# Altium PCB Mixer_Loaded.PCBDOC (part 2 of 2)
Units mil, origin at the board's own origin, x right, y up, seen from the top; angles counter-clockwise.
Board outline 16350 x 11350 mil, 2 copper layers (Top Layer, Bottom Layer); 554 components, 386 nets, 1551 pads, 0 vias.
Unrouted connection lines stored in the file: 1047.
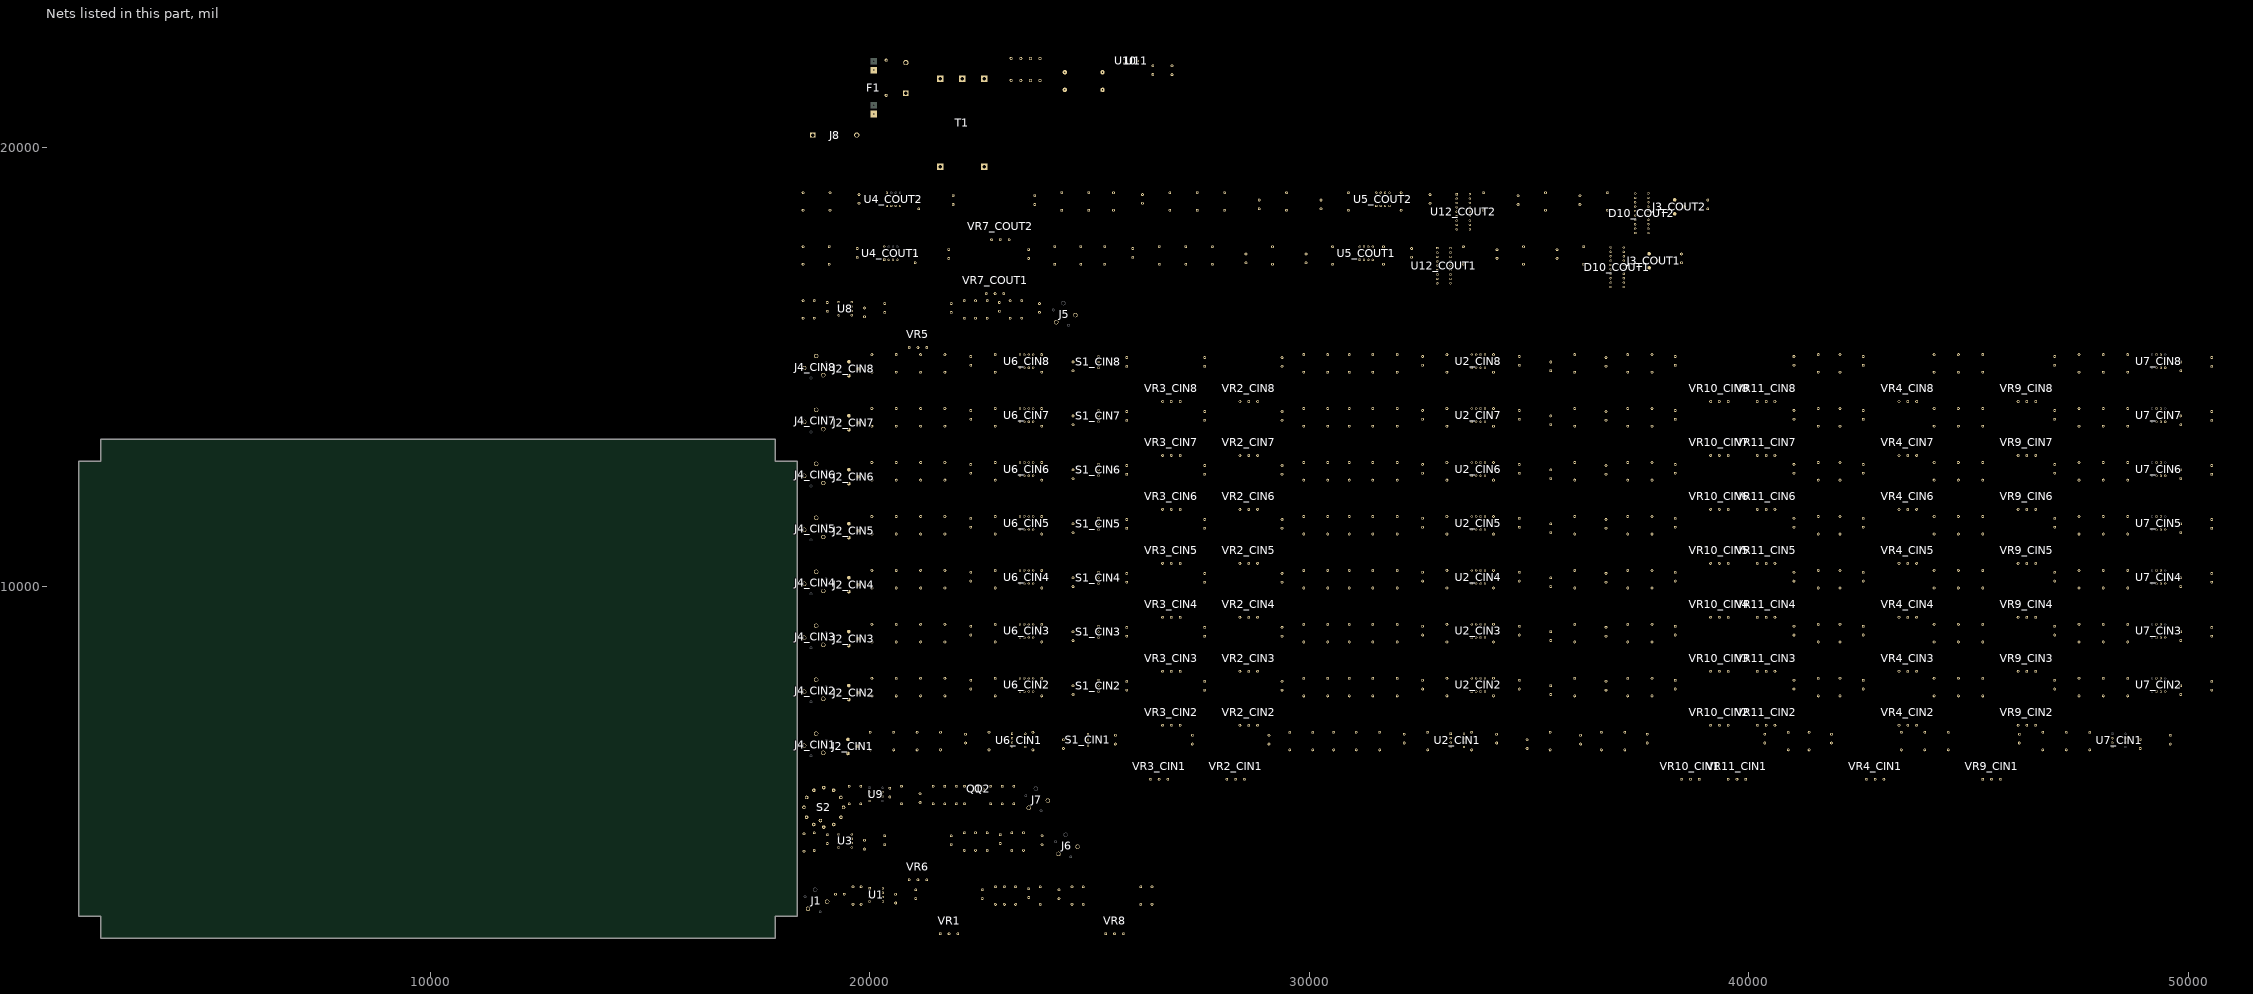
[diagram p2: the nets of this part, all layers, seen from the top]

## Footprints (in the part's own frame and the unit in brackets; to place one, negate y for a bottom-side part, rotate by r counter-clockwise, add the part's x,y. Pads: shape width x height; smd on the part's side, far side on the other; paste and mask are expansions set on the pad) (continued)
FUSE [mil]
  rect 150x150 hole 30: 1(0,0) 1(200,0) 2(1000,0) 2(1200,0)
  Top Layer region: 150,75 50,75 50,-75 150,-75
  Top Layer region: 1150,75 1050,75 1050,-75 1150,-75
  Bottom Layer region: 150,75 50,75 50,-75 150,-75
  Bottom Layer region: 1150,75 1050,75 1050,-75 1150,-75
  silkscreen extent -100,-100 1300,100
IEC-MAINS [mil]
  rect 120x120 hole 80: 1(0,0)
  round 120 hole 80: 2(500,0) 3(1000,0)
  silkscreen extent -250,-250 1250,1750
JACK-6.25MM [mil]
  round 60 hole 39: 0(-251,94) 0(94,-251)
  round 100 hole 78: 1(251,-22) 2(-22,251) 3(-184,-184)
  silkscreen extent -315,-315 315,315
"LED - 10 BAR HORIZONTAL" [mil]
  rect 50x50 hole 32: 1(0,0)
  round 50 hole 32: 2(300,0) 3(0,100) 4(300,100) 5(0,200) 6(300,200) 7(0,300) 8(300,300) 9(0,400) 10(300,400) 11(0,500) 12(300,500) 13(0,600) 14(300,600) 15(0,700) 16(300,700) 17(0,800) 18(300,800) 19(0,900) 20(300,900)
  silkscreen extent -50,-50 350,950
"POT - 24MM" [mil]
  round 62 hole 35: 1(-200,-600) 2(0,-600) 3(200,-600)
  round 50 hole 236.22 unplated: MNT(0,0)
  Keep-Out Layer circle w10: c0,0 r210
  silkscreen extent -500,-670 500,500
RAD0.2 [mil]
  round 62 hole 28: 1(0,0) 2(200,0)
  silkscreen extent -75,-75 275,75
RAD0.8 [mil]
  round 70 hole 40: 1(0,0) 2(800,0)
  silkscreen extent -75,-125 875,125
RB.2/.4 [mil]
  round 62 hole 28: 1(0,0) 2(-200,0)
  silkscreen extent -300,-200 200,200
RB.2/.4-NP [mil]
  round 62 hole 28: 1(0,0) 2(-200,0)
  silkscreen extent -300,-200 100,200
RB.4/.8 [mil]
  round 100 hole 28: 1(0,0) 2(-400,0)
  silkscreen extent -600,-400 350,400
SW-12WAY [mil]
  round 80 hole 40: 1(225,389.71) 2(389.71,225) 3(450,0) 4(389.71,-225) 5(225,-389.71) 6(0,-450) 7(-225,-389.71) 8(-389.71,-225) 9(-450,0) 10(-389.71,225) 11(-225,389.71) 12(0,450) 13(-75,-300)
  silkscreen extent -500,-500 500,500
SW-MAINS [mil]
  rect 120x120 hole 80: 1(0,0)
  round 120 hole 80: 2(700,0)
  silkscreen extent -120,-225 830,225
SW-SPDT [mil]
  rect 50x50 hole 32: 1(0,0)
  round 50 hole 32: 2(130,0) 3(260,0)
  silkscreen extent -70,-75 330,75
TO-92A [mil]
  round 50 hole 30: 1(0,0) 2(50,-50) 3(100,0)
  silkscreen extent -40,-90 140,40
TRANSFORMER [mil]
  rect 150x150 hole 80: 1(0,0) 2(0,1000) 3(2000,1000) 4(2000,500) 5(2000,0)
  silkscreen extent -500,-500 2500,1500
XLR-FEMALE [mm]
  round 2.032 smd: 1(-4.05,0.8) 2(4.05,0.8) 3(0,-4.7)
  silkscreen extent -9,-9 9,9
XLR-MALE [mm]
  round 2.032 smd: 1(4.05,0.8) 2(-4.05,0.8) 3(0,-4.7)
  silkscreen extent -9,-9 9,9

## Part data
C1 C2 C3 C4 C5 C6 C7_CIN1 C7_CIN2 C7_CIN3 C7_CIN4 C7_CIN5 C7_CIN6 C7_CIN7 C7_CIN8 C8_CIN1 C8_CIN2 C8_CIN3 C8_CIN4 C8_CIN5 C8_CIN6 C8_CIN7 C8_CIN8 C9_CIN1 C9_CIN2 C9_CIN3 C9_CIN4 C9_CIN5 C9_CIN6 C9_CIN7 C9_CIN8 C10_CIN1 C10_CIN2 C10_CIN3 C10_CIN4 C10_CIN5 C10_CIN6 C10_CIN7 C10_CIN8 C11 C12 C13_COUT1 C13_COUT2 C14_COUT1 C14_COUT2 C24 C25_CIN1 C25_CIN2 C25_CIN3 C25_CIN4 C25_CIN5 C25_CIN6 C25_CIN7 C25_CIN8 C26_CIN1 C26_CIN2 C26_CIN3 C26_CIN4 C26_CIN5 C26_CIN6 C26_CIN7 C26_CIN8 C27_CIN1 C27_CIN2 C27_CIN3 C27_CIN4 C27_CIN5 C27_CIN6 C27_CIN7 C27_CIN8 C28_COUT1 C28_COUT2 C29_CIN1 C29_CIN2 C29_CIN3 C29_CIN4 C29_CIN5 C29_CIN6 C29_CIN7 C29_CIN8 C30_CIN1 C30_CIN2 C30_CIN3 C30_CIN4 C30_CIN5 C30_CIN6 C30_CIN7 C30_CIN8 C31_CIN1 C31_CIN2 C31_CIN3 C31_CIN4 C31_CIN5 C31_CIN6 C31_CIN7 C31_CIN8 C32_CIN1 C32_CIN2 C32_CIN3 C32_CIN4 C32_CIN5 C32_CIN6 C32_CIN7 C32_CIN8 C33_CIN1 C33_CIN2 C33_CIN3 C33_CIN4 C33_CIN5 C33_CIN6 C33_CIN7 C33_CIN8 C34 C35 C36_COUT1 C36_COUT2 C37 C38 C39_COUT1 C39_COUT2 C40_COUT1 C40_COUT2 C41 C42 C43 C44 C51_COUT1 C51_COUT2: "Capacitor"
C15 C16_CIN1 C16_CIN2 C16_CIN3 C16_CIN4 C16_CIN5 C16_CIN6 C16_CIN7 C16_CIN8 C17_CIN1 C17_CIN2 C17_CIN3 C17_CIN4 C17_CIN5 C17_CIN6 C17_CIN7 C17_CIN8 C18_CIN1 C18_CIN2 C18_CIN3 C18_CIN4 C18_CIN5 C18_CIN6 C18_CIN7 C18_CIN8 C19 C20 C21 C22_COUT1 C22_COUT2 C23_COUT1 C23_COUT2 C45 C46 C47 C48 C49_COUT1 C49_COUT2 C50_COUT1 C50_COUT2: "Bi-Polar Capacitor"
D1 D2 D3 D4 D5 D6: "Diode"
F1: "Fuse"
J2_CIN1 J2_CIN2 J2_CIN3 J2_CIN4 J2_CIN5 J2_CIN6 J2_CIN7 J2_CIN8 J3_COUT1 J3_COUT2: "XLR connector, PCB mounted"
J8: "Connector"
Q1: "NPN BJT"
Q2: "PNP BJT"
R1 R2 R3_CIN1 R3_CIN2 R3_CIN3 R3_CIN4 R3_CIN5 R3_CIN6 R3_CIN7 R3_CIN8 R4_CIN1 R4_CIN2 R4_CIN3 R4_CIN4 R4_CIN5 R4_CIN6 R4_CIN7 R4_CIN8 R5_CIN1 R5_CIN2 R5_CIN3 R5_CIN4 R5_CIN5 R5_CIN6 R5_CIN7 R5_CIN8 R6_CIN1 R6_CIN2 R6_CIN3 R6_CIN4 R6_CIN5 R6_CIN6 R6_CIN7 R6_CIN8 R7 R8_COUT1 R8_COUT2 R9 R10 R11_CIN1 R11_CIN2 R11_CIN3 R11_CIN4 R11_CIN5 R11_CIN6 R11_CIN7 R11_CIN8 R12_CIN1 R12_CIN2 R12_CIN3 R12_CIN4 R12_CIN5 R12_CIN6 R12_CIN7 R12_CIN8 R13 R14 R15_COUT1 R15_COUT2 R16 R17 R18 R19 R20_CIN1 R20_CIN2 R20_CIN3 R20_CIN4 R20_CIN5 R20_CIN6 R20_CIN7 R20_CIN8 R21_CIN1 R21_CIN2 R21_CIN3 R21_CIN4 R21_CIN5 R21_CIN6 R21_CIN7 R21_CIN8 R22_CIN1 R22_CIN2 R22_CIN3 R22_CIN4 R22_CIN5 R22_CIN6 R22_CIN7 R22_CIN8 R23_CIN1 R23_CIN2 R23_CIN3 R23_CIN4 R23_CIN5 R23_CIN6 R23_CIN7 R23_CIN8 R24 R25_CIN1 R25_CIN2 R25_CIN3 R25_CIN4 R25_CIN5 R25_CIN6 R25_CIN7 R25_CIN8 R26_CIN1 R26_CIN2 R26_CIN3 R26_CIN4 R26_CIN5 R26_CIN6 R26_CIN7 R26_CIN8 R27_CIN1 R27_CIN2 R27_CIN3 R27_CIN4 R27_CIN5 R27_CIN6 R27_CIN7 R27_CIN8 R28_CIN1 R28_CIN2 R28_CIN3 R28_CIN4 R28_CIN5 R28_CIN6 R28_CIN7 R28_CIN8 R29 R30 R31 R32 R33 R34 R35 R36 R37_COUT1 R37_COUT2 R38_COUT1 R38_COUT2 R39 R40_CIN1 R40_CIN2 R40_CIN3 R40_CIN4 R40_CIN5 R40_CIN6 R40_CIN7 R40_CIN8 R41_CIN1 R41_CIN2 R41_CIN3 R41_CIN4 R41_CIN5 R41_CIN6 R41_CIN7 R41_CIN8 R42_COUT1 R42_COUT2 R43_CIN1 R43_CIN2 R43_CIN3 R43_CIN4 R43_CIN5 R43_CIN6 R43_CIN7 R43_CIN8 R44_COUT1 R44_COUT2 R45_CIN1 R45_CIN2 R45_CIN3 R45_CIN4 R45_CIN5 R45_CIN6 R45_CIN7 R45_CIN8 R46_CIN1 R46_CIN2 R46_CIN3 R46_CIN4 R46_CIN5 R46_CIN6 R46_CIN7 R46_CIN8 R47_CIN1 R47_CIN2 R47_CIN3 R47_CIN4 R47_CIN5 R47_CIN6 R47_CIN7 R47_CIN8 R48_CIN1 R48_CIN2 R48_CIN3 R48_CIN4 R48_CIN5 R48_CIN6 R48_CIN7 R48_CIN8 R49_CIN1 R49_CIN2 R49_CIN3 R49_CIN4 R49_CIN5 R49_CIN6 R49_CIN7 R49_CIN8 R50_CIN1 R50_CIN2 R50_CIN3 R50_CIN4 R50_CIN5 R50_CIN6 R50_CIN7 R50_CIN8 R51_CIN1 R51_CIN2 R51_CIN3 R51_CIN4 R51_CIN5 R51_CIN6 R51_CIN7 R51_CIN8 R52 R53 R54 R55_COUT1 R55_COUT2 R56_COUT1 R56_COUT2 R57 R58 R59 R60_COUT1 R60_COUT2 R61 R62 R63_COUT1 R63_COUT2 R64_COUT1 R64_COUT2 R65_COUT1 R65_COUT2 R66 R67 R68 R69_COUT1 R69_COUT2 R70_COUT1 R70_COUT2: "Resistor"
T1: "Center-Tapped Transformer"
U1 U2_CIN1 U2_CIN2 U2_CIN3 U2_CIN4 U2_CIN5 U2_CIN6 U2_CIN7 U2_CIN8 U3 U4_COUT1 U4_COUT2 U5_COUT1 U5_COUT2 U8: "Fast Settling Dual Operational Amplifier"
U6_CIN1 U6_CIN2 U6_CIN3 U6_CIN4 U6_CIN5 U6_CIN6 U6_CIN7 U6_CIN8: "Self-Contained Audio Preamplifier"
U7_CIN1 U7_CIN2 U7_CIN3 U7_CIN4 U7_CIN5 U7_CIN6 U7_CIN7 U7_CIN8: "Low Noise, High Speed Precision Operational Amplifier"
U9: "Low-Noise  JFET-Input Operational Amplifiers"
U10 U11: "Very Low Drop Voltage Regulators With Inhibit"
U12_COUT1 U12_COUT2: "Dot/Bar Display Driver"
VR1 VR2_CIN1 VR2_CIN2 VR2_CIN3 VR2_CIN4 VR2_CIN5 VR2_CIN6 VR2_CIN7 VR2_CIN8 VR3_CIN1 VR3_CIN2 VR3_CIN3 VR3_CIN4 VR3_CIN5 VR3_CIN6 VR3_CIN7 VR3_CIN8 VR4_CIN1 VR4_CIN2 VR4_CIN3 VR4_CIN4 VR4_CIN5 VR4_CIN6 VR4_CIN7 VR4_CIN8 VR5 VR6 VR7_COUT1 VR7_COUT2 VR8 VR9_CIN1 VR9_CIN2 VR9_CIN3 VR9_CIN4 VR9_CIN5 VR9_CIN6 VR9_CIN7 VR9_CIN8 VR10_CIN1 VR10_CIN2 VR10_CIN3 VR10_CIN4 VR10_CIN5 VR10_CIN6 VR10_CIN7 VR10_CIN8 VR11_CIN1 VR11_CIN2 VR11_CIN3 VR11_CIN4 VR11_CIN5 VR11_CIN6 VR11_CIN7 VR11_CIN8: "Potentiometer"

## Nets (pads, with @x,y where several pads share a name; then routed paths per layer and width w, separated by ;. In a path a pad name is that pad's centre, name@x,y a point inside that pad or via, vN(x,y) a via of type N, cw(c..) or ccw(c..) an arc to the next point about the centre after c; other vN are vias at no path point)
+15V: C15.1 C16_CIN1.1 C16_CIN2.1 C16_CIN3.1 C16_CIN4.1 C16_CIN5.1 C16_CIN6.1 C16_CIN7.1 C16_CIN8.1 C17_CIN1.1 C17_CIN2.1 C17_CIN3.1 C17_CIN4.1 C17_CIN5.1 C17_CIN6.1 C17_CIN7.1 C17_CIN8.1 C18_CIN1.1 C18_CIN2.1 C18_CIN3.1 C18_CIN4.1 C18_CIN5.1 C18_CIN6.1 C18_CIN7.1 C18_CIN8.1 C19.1 C20.1 C21.1 C22_COUT1.1 C22_COUT2.1 C23_COUT1.1 C23_COUT2.1 C47.1 C49_COUT1.1 C49_COUT2.1 Q1.1 R53.2 R69_COUT1.1 R69_COUT2.1 U1.4 U2_CIN1.8 U2_CIN2.8 U2_CIN3.8 U2_CIN4.8 U2_CIN5.8 U2_CIN6.8 U2_CIN7.8 U2_CIN8.8 U3.8 U4_COUT1.8 U4_COUT2.8 U5_COUT1.8 U5_COUT2.8 U6_CIN1.7 U6_CIN2.7 U6_CIN3.7 U6_CIN4.7 U6_CIN5.7 U6_CIN6.7 U6_CIN7.7 U6_CIN8.7 U7_CIN1.7 U7_CIN2.7 U7_CIN3.7 U7_CIN4.7 U7_CIN5.7 U7_CIN6.7 U7_CIN7.7 U7_CIN8.7 U8.8 U9.7 U10.3 U12_COUT1.3 U12_COUT1.9 U12_COUT2.3 U12_COUT2.9
-15V: C15.2 C16_CIN1.2 C16_CIN2.2 C16_CIN3.2 C16_CIN4.2 C16_CIN5.2 C16_CIN6.2 C16_CIN7.2 C16_CIN8.2 C17_CIN1.2 C17_CIN2.2 C17_CIN3.2 C17_CIN4.2 C17_CIN5.2 C17_CIN6.2 C17_CIN7.2 C17_CIN8.2 C18_CIN1.2 C18_CIN2.2 C18_CIN3.2 C18_CIN4.2 C18_CIN5.2 C18_CIN6.2 C18_CIN7.2 C18_CIN8.2 C19.2 C20.2 C21.2 C22_COUT1.2 C22_COUT2.2 C23_COUT1.2 C23_COUT2.2 C48.2 Q2.1 R54.1 U1.8 U2_CIN1.4 U2_CIN2.4 U2_CIN3.4 U2_CIN4.4 U2_CIN5.4 U2_CIN6.4 U2_CIN7.4 U2_CIN8.4 U3.4 U4_COUT1.4 U4_COUT2.4 U5_COUT1.4 U5_COUT2.4 U6_CIN1.4 U6_CIN2.4 U6_CIN3.4 U6_CIN4.4 U6_CIN5.4 U6_CIN6.4 U6_CIN7.4 U6_CIN8.4 U7_CIN1.4 U7_CIN2.4 U7_CIN3.4 U7_CIN4.4 U7_CIN5.4 U7_CIN6.4 U7_CIN7.4 U7_CIN8.4 U8.4 U9.4 U11.1
A_FUSE: C44.2 F1.2@20087,21753 S3.2
A_IN: F1.1@20087,20753 J8.1
A_SWITCH: C44.1 S3.1 T1.1
GND: C45.2 C46.1 C47.2 C48.1 C49_COUT1.2 C49_COUT2.2 C50_COUT1.2 C50_COUT2.2 J1.3 J2_CIN1.1 J2_CIN2.1 J2_CIN3.1 J2_CIN4.1 J2_CIN5.1 J2_CIN6.1 J2_CIN7.1 J2_CIN8.1 J3_COUT1.1 J3_COUT2.1 J4_CIN1.3 J4_CIN2.3 J4_CIN3.3 J4_CIN4.3 J4_CIN5.3 J4_CIN6.3 J4_CIN7.3 J4_CIN8.3 J5.3 J6.3 J7.3 R1.1 R2.1 R3_CIN1.2 R3_CIN2.2 R3_CIN3.2 R3_CIN4.2 R3_CIN5.2 R3_CIN6.2 R3_CIN7.2 R3_CIN8.2 R7.1 R8_COUT1.1 R8_COUT2.1 R24.2 R27_CIN1.1 R27_CIN2.1 R27_CIN3.1 R27_CIN4.1 R27_CIN5.1 R27_CIN6.1 R27_CIN7.1 R27_CIN8.1 R28_CIN1.1 R28_CIN2.1 R28_CIN3.1 R28_CIN4.1 R28_CIN5.1 R28_CIN6.1 R28_CIN7.1 R28_CIN8.1 R30.1 R31.2 R34.1 R35.2 R38_COUT1.2 R38_COUT2.2 R48_CIN1.1 R48_CIN2.1 R48_CIN3.1 R48_CIN4.1 R48_CIN5.1 R48_CIN6.1 R48_CIN7.1 R48_CIN8.1 R49_CIN1.1 R49_CIN2.1 R49_CIN3.1 R49_CIN4.1 R49_CIN5.1 R49_CIN6.1 R49_CIN7.1 R49_CIN8.1 R70_COUT1.1 R70_COUT2.1 T1.4 U3.3 U4_COUT1.3 U4_COUT2.3 U5_COUT1.3 U5_COUT2.3 U6_CIN1.5 U6_CIN2.5 U6_CIN3.5 U6_CIN4.5 U6_CIN5.5 U6_CIN6.5 U6_CIN7.5 U6_CIN8.5 U7_CIN1.3 U7_CIN2.3 U7_CIN3.3 U7_CIN4.3 U7_CIN5.3 U7_CIN6.3 U7_CIN7.3 U7_CIN8.3 U8.3 U10.2 U11.3 U12_COUT1.2 U12_COUT1.4 U12_COUT2.2 U12_COUT2.4 VR1.3 VR2_CIN1.3 VR2_CIN2.3 VR2_CIN3.3 VR2_CIN4.3 VR2_CIN5.3 VR2_CIN6.3 VR2_CIN7.3 VR2_CIN8.3 VR3_CIN1.3 VR3_CIN2.3 VR3_CIN3.3 VR3_CIN4.3 VR3_CIN5.3 VR3_CIN6.3 VR3_CIN7.3 VR3_CIN8.3 VR4_CIN1.3 VR4_CIN2.3 VR4_CIN3.3 VR4_CIN4.3 VR4_CIN5.3 VR4_CIN6.3 VR4_CIN7.3 VR4_CIN8.3 VR5.3 VR6.3 VR7_COUT1.3 VR7_COUT2.3 VR8.2 VR9_CIN1.2 VR9_CIN2.2 VR9_CIN3.2 VR9_CIN4.2 VR9_CIN5.2 VR9_CIN6.2 VR9_CIN7.2 VR9_CIN8.2
HEADPHONE1: R51_CIN1.2 S2.8
HEADPHONE2: R51_CIN2.2 S2.7
HEADPHONE3: R51_CIN3.2 S2.6
HEADPHONE4: R51_CIN4.2 S2.5
HEADPHONE5: R51_CIN5.2 S2.4
HEADPHONE6: R51_CIN6.2 S2.3
HEADPHONE7: R51_CIN7.2 S2.2
HEADPHONE8: R51_CIN8.2 S2.1
MB1: R17.2 R22_CIN1.2 R22_CIN2.2 R22_CIN3.2 R22_CIN4.2 R22_CIN5.2 R22_CIN6.2 R22_CIN7.2 R22_CIN8.2 R37_COUT1.1 S2.11
MB2: R19.2 R23_CIN1.2 R23_CIN2.2 R23_CIN3.2 R23_CIN4.2 R23_CIN5.2 R23_CIN6.2 R23_CIN7.2 R23_CIN8.2 R37_COUT2.1 S2.12
NetC1_1: C1.1 J1.1
NetC1_2: C1.2 R1.2 R9.1
NetC2_1: C2.1 VR1.2
NetC2_2: C2.2 R2.2 R10.1
NetC3_1: C3.1 VR5.2
NetC3_2: C3.2 R13.1
NetC4_1: C4.1 VR6.2
NetC4_2: C4.2 R14.1
NetC5_1: C5.1 U1.1 U1.2
NetC5_2: C5.2 VR1.1
NetC6_1: C6.1 C24.2 R39.1 U1.7
NetC6_2: C6.2 R16.1 R18.1
NetC7_CIN1_1: C7_CIN1.1 VR2_CIN1.2
NetC7_CIN1_2: C7_CIN1.2 R3_CIN1.1 R11_CIN1.1
NetC7_CIN2_1: C7_CIN2.1 VR2_CIN2.2
NetC7_CIN2_2: C7_CIN2.2 R3_CIN2.1 R11_CIN2.1
NetC7_CIN3_1: C7_CIN3.1 VR2_CIN3.2
NetC7_CIN3_2: C7_CIN3.2 R3_CIN3.1 R11_CIN3.1
NetC7_CIN4_1: C7_CIN4.1 VR2_CIN4.2
NetC7_CIN4_2: C7_CIN4.2 R3_CIN4.1 R11_CIN4.1
NetC7_CIN5_1: C7_CIN5.1 VR2_CIN5.2
NetC7_CIN5_2: C7_CIN5.2 R3_CIN5.1 R11_CIN5.1
NetC7_CIN6_1: C7_CIN6.1 VR2_CIN6.2
NetC7_CIN6_2: C7_CIN6.2 R3_CIN6.1 R11_CIN6.1
NetC7_CIN7_1: C7_CIN7.1 VR2_CIN7.2
NetC7_CIN7_2: C7_CIN7.2 R3_CIN7.1 R11_CIN7.1
NetC7_CIN8_1: C7_CIN8.1 VR2_CIN8.2
NetC7_CIN8_2: C7_CIN8.2 R3_CIN8.1 R11_CIN8.1
NetC8_CIN1_1: C8_CIN1.1 C26_CIN1.2 R40_CIN1.2 U2_CIN1.1
NetC8_CIN1_2: C8_CIN1.2 R4_CIN1.1 R46_CIN1.2
NetC8_CIN2_1: C8_CIN2.1 C26_CIN2.2 R40_CIN2.2 U2_CIN2.1
NetC8_CIN2_2: C8_CIN2.2 R4_CIN2.1 R46_CIN2.2
NetC8_CIN3_1: C8_CIN3.1 C26_CIN3.2 R40_CIN3.2 U2_CIN3.1
NetC8_CIN3_2: C8_CIN3.2 R4_CIN3.1 R46_CIN3.2
NetC8_CIN4_1: C8_CIN4.1 C26_CIN4.2 R40_CIN4.2 U2_CIN4.1
NetC8_CIN4_2: C8_CIN4.2 R4_CIN4.1 R46_CIN4.2
NetC8_CIN5_1: C8_CIN5.1 C26_CIN5.2 R40_CIN5.2 U2_CIN5.1
NetC8_CIN5_2: C8_CIN5.2 R4_CIN5.1 R46_CIN5.2
NetC8_CIN6_1: C8_CIN6.1 C26_CIN6.2 R40_CIN6.2 U2_CIN6.1
NetC8_CIN6_2: C8_CIN6.2 R4_CIN6.1 R46_CIN6.2
NetC8_CIN7_1: C8_CIN7.1 C26_CIN7.2 R40_CIN7.2 U2_CIN7.1
NetC8_CIN7_2: C8_CIN7.2 R4_CIN7.1 R46_CIN7.2
NetC8_CIN8_1: C8_CIN8.1 C26_CIN8.2 R40_CIN8.2 U2_CIN8.1
NetC8_CIN8_2: C8_CIN8.2 R4_CIN8.1 R46_CIN8.2
NetC9_CIN1_1: C9_CIN1.1 C33_CIN1.2 R6_CIN1.2 R47_CIN1.2 U7_CIN1.6
NetC9_CIN1_2: C9_CIN1.2 R20_CIN1.1 R21_CIN1.1 R51_CIN1.1 VR4_CIN1.1
NetC9_CIN2_1: C9_CIN2.1 C33_CIN2.2 R6_CIN2.2 R47_CIN2.2 U7_CIN2.6
NetC9_CIN2_2: C9_CIN2.2 R20_CIN2.1 R21_CIN2.1 R51_CIN2.1 VR4_CIN2.1
NetC9_CIN3_1: C9_CIN3.1 C33_CIN3.2 R6_CIN3.2 R47_CIN3.2 U7_CIN3.6
NetC9_CIN3_2: C9_CIN3.2 R20_CIN3.1 R21_CIN3.1 R51_CIN3.1 VR4_CIN3.1
NetC9_CIN4_1: C9_CIN4.1 C33_CIN4.2 R6_CIN4.2 R47_CIN4.2 U7_CIN4.6
NetC9_CIN4_2: C9_CIN4.2 R20_CIN4.1 R21_CIN4.1 R51_CIN4.1 VR4_CIN4.1
NetC9_CIN5_1: C9_CIN5.1 C33_CIN5.2 R6_CIN5.2 R47_CIN5.2 U7_CIN5.6
NetC9_CIN5_2: C9_CIN5.2 R20_CIN5.1 R21_CIN5.1 R51_CIN5.1 VR4_CIN5.1
NetC9_CIN6_1: C9_CIN6.1 C33_CIN6.2 R6_CIN6.2 R47_CIN6.2 U7_CIN6.6
NetC9_CIN6_2: C9_CIN6.2 R20_CIN6.1 R21_CIN6.1 R51_CIN6.1 VR4_CIN6.1
NetC9_CIN7_1: C9_CIN7.1 C33_CIN7.2 R6_CIN7.2 R47_CIN7.2 U7_CIN7.6
NetC9_CIN7_2: C9_CIN7.2 R20_CIN7.1 R21_CIN7.1 R51_CIN7.1 VR4_CIN7.1
NetC9_CIN8_1: C9_CIN8.1 C33_CIN8.2 R6_CIN8.2 R47_CIN8.2 U7_CIN8.6
NetC9_CIN8_2: C9_CIN8.2 R20_CIN8.1 R21_CIN8.1 R51_CIN8.1 VR4_CIN8.1
NetC10_CIN1_1: C10_CIN1.1 VR3_CIN1.2
NetC10_CIN1_2: C10_CIN1.2 R12_CIN1.1
NetC10_CIN2_1: C10_CIN2.1 VR3_CIN2.2
NetC10_CIN2_2: C10_CIN2.2 R12_CIN2.1
NetC10_CIN3_1: C10_CIN3.1 VR3_CIN3.2
NetC10_CIN3_2: C10_CIN3.2 R12_CIN3.1
NetC10_CIN4_1: C10_CIN4.1 VR3_CIN4.2
NetC10_CIN4_2: C10_CIN4.2 R12_CIN4.1
NetC10_CIN5_1: C10_CIN5.1 VR3_CIN5.2
NetC10_CIN5_2: C10_CIN5.2 R12_CIN5.1
NetC10_CIN6_1: C10_CIN6.1 VR3_CIN6.2
NetC10_CIN6_2: C10_CIN6.2 R12_CIN6.1
NetC10_CIN7_1: C10_CIN7.1 VR3_CIN7.2
NetC10_CIN7_2: C10_CIN7.2 R12_CIN7.1
NetC10_CIN8_1: C10_CIN8.1 VR3_CIN8.2
NetC10_CIN8_2: C10_CIN8.2 R12_CIN8.1
NetC11_1: C11.1 C34.2 R57.2 U8.1
NetC11_2: C11.2 VR5.1
NetC12_1: C12.1 C35.2 R58.2 U3.1
NetC12_2: C12.2 VR6.1
NetC13_COUT1_1: C13_COUT1.1 C36_COUT1.2 R60_COUT1.2 U4_COUT1.1
NetC13_COUT1_2: C13_COUT1.2 VR7_COUT1.1
NetC13_COUT2_1: C13_COUT2.1 C36_COUT2.2 R60_COUT2.2 U4_COUT2.1
NetC13_COUT2_2: C13_COUT2.2 VR7_COUT2.1
NetC14_COUT1_1: C14_COUT1.1 VR7_COUT1.2
NetC14_COUT1_2: C14_COUT1.2 R15_COUT1.1
NetC14_COUT2_1: C14_COUT2.1 VR7_COUT2.2
NetC14_COUT2_2: C14_COUT2.2 R15_COUT2.1
NetC24_1: C24.1 R24.1 R39.2 U1.6
NetC25_CIN1_1: C25_CIN1.1 J2_CIN1.2 R25_CIN1.2 R48_CIN1.2 U6_CIN1.2
NetC25_CIN1_2: C25_CIN1.2 J2_CIN1.3 R26_CIN1.2 R49_CIN1.2 U6_CIN1.3
NetC25_CIN2_1: C25_CIN2.1 J2_CIN2.2 R25_CIN2.2 R48_CIN2.2 U6_CIN2.2
NetC25_CIN2_2: C25_CIN2.2 J2_CIN2.3 R26_CIN2.2 R49_CIN2.2 U6_CIN2.3
NetC25_CIN3_1: C25_CIN3.1 J2_CIN3.2 R25_CIN3.2 R48_CIN3.2 U6_CIN3.2
NetC25_CIN3_2: C25_CIN3.2 J2_CIN3.3 R26_CIN3.2 R49_CIN3.2 U6_CIN3.3
NetC25_CIN4_1: C25_CIN4.1 J2_CIN4.2 R25_CIN4.2 R48_CIN4.2 U6_CIN4.2
NetC25_CIN4_2: C25_CIN4.2 J2_CIN4.3 R26_CIN4.2 R49_CIN4.2 U6_CIN4.3
NetC25_CIN5_1: C25_CIN5.1 J2_CIN5.2 R25_CIN5.2 R48_CIN5.2 U6_CIN5.2
NetC25_CIN5_2: C25_CIN5.2 J2_CIN5.3 R26_CIN5.2 R49_CIN5.2 U6_CIN5.3
NetC25_CIN6_1: C25_CIN6.1 J2_CIN6.2 R25_CIN6.2 R48_CIN6.2 U6_CIN6.2
NetC25_CIN6_2: C25_CIN6.2 J2_CIN6.3 R26_CIN6.2 R49_CIN6.2 U6_CIN6.3
NetC25_CIN7_1: C25_CIN7.1 J2_CIN7.2 R25_CIN7.2 R48_CIN7.2 U6_CIN7.2
NetC25_CIN7_2: C25_CIN7.2 J2_CIN7.3 R26_CIN7.2 R49_CIN7.2 U6_CIN7.3
NetC25_CIN8_1: C25_CIN8.1 J2_CIN8.2 R25_CIN8.2 R48_CIN8.2 U6_CIN8.2
NetC25_CIN8_2: C25_CIN8.2 J2_CIN8.3 R26_CIN8.2 R49_CIN8.2 U6_CIN8.3
NetC26_CIN1_1: C26_CIN1.1 R27_CIN1.2 R40_CIN1.1 U2_CIN1.2
NetC26_CIN2_1: C26_CIN2.1 R27_CIN2.2 R40_CIN2.1 U2_CIN2.2
NetC26_CIN3_1: C26_CIN3.1 R27_CIN3.2 R40_CIN3.1 U2_CIN3.2
NetC26_CIN4_1: C26_CIN4.1 R27_CIN4.2 R40_CIN4.1 U2_CIN4.2
NetC26_CIN5_1: C26_CIN5.1 R27_CIN5.2 R40_CIN5.1 U2_CIN5.2
NetC26_CIN6_1: C26_CIN6.1 R27_CIN6.2 R40_CIN6.1 U2_CIN6.2
NetC26_CIN7_1: C26_CIN7.1 R27_CIN7.2 R40_CIN7.1 U2_CIN7.2
NetC26_CIN8_1: C26_CIN8.1 R27_CIN8.2 R40_CIN8.1 U2_CIN8.2
NetC27_CIN1_1: C27_CIN1.1 R28_CIN1.2 R41_CIN1.1 U2_CIN1.6
NetC27_CIN1_2: C27_CIN1.2 R41_CIN1.2 R50_CIN1.1 U2_CIN1.7
NetC27_CIN2_1: C27_CIN2.1 R28_CIN2.2 R41_CIN2.1 U2_CIN2.6
NetC27_CIN2_2: C27_CIN2.2 R41_CIN2.2 R50_CIN2.1 U2_CIN2.7
NetC27_CIN3_1: C27_CIN3.1 R28_CIN3.2 R41_CIN3.1 U2_CIN3.6
NetC27_CIN3_2: C27_CIN3.2 R41_CIN3.2 R50_CIN3.1 U2_CIN3.7
NetC27_CIN4_1: C27_CIN4.1 R28_CIN4.2 R41_CIN4.1 U2_CIN4.6
NetC27_CIN4_2: C27_CIN4.2 R41_CIN4.2 R50_CIN4.1 U2_CIN4.7
NetC27_CIN5_1: C27_CIN5.1 R28_CIN5.2 R41_CIN5.1 U2_CIN5.6
NetC27_CIN5_2: C27_CIN5.2 R41_CIN5.2 R50_CIN5.1 U2_CIN5.7
NetC27_CIN6_1: C27_CIN6.1 R28_CIN6.2 R41_CIN6.1 U2_CIN6.6
NetC27_CIN6_2: C27_CIN6.2 R41_CIN6.2 R50_CIN6.1 U2_CIN6.7
NetC27_CIN7_1: C27_CIN7.1 R28_CIN7.2 R41_CIN7.1 U2_CIN7.6
NetC27_CIN7_2: C27_CIN7.2 R41_CIN7.2 R50_CIN7.1 U2_CIN7.7
NetC27_CIN8_1: C27_CIN8.1 R28_CIN8.2 R41_CIN8.1 U2_CIN8.6
NetC27_CIN8_2: C27_CIN8.2 R41_CIN8.2 R50_CIN8.1 U2_CIN8.7
NetC28_COUT1_1: C28_COUT1.1 R38_COUT1.1 R42_COUT1.2 U5_COUT1.6
NetC28_COUT1_2: C28_COUT1.2 C39_COUT1.1 R42_COUT1.1 R55_COUT1.2 R63_COUT1.2 R64_COUT1.1
NetC28_COUT2_1: C28_COUT2.1 R38_COUT2.1 R42_COUT2.2 U5_COUT2.6
NetC28_COUT2_2: C28_COUT2.2 C39_COUT2.1 R42_COUT2.1 R55_COUT2.2 R63_COUT2.2 R64_COUT2.1
NetC29_CIN1_1: C29_CIN1.1 R4_CIN1.2 VR10_CIN1.3
NetC29_CIN1_2: C29_CIN1.2 R6_CIN1.1 VR10_CIN1.1
NetC29_CIN2_1: C29_CIN2.1 R4_CIN2.2 VR10_CIN2.3
NetC29_CIN2_2: C29_CIN2.2 R6_CIN2.1 VR10_CIN2.1
NetC29_CIN3_1: C29_CIN3.1 R4_CIN3.2 VR10_CIN3.3
NetC29_CIN3_2: C29_CIN3.2 R6_CIN3.1 VR10_CIN3.1
NetC29_CIN4_1: C29_CIN4.1 R4_CIN4.2 VR10_CIN4.3
NetC29_CIN4_2: C29_CIN4.2 R6_CIN4.1 VR10_CIN4.1
NetC29_CIN5_1: C29_CIN5.1 R4_CIN5.2 VR10_CIN5.3
NetC29_CIN5_2: C29_CIN5.2 R6_CIN5.1 VR10_CIN5.1
NetC29_CIN6_1: C29_CIN6.1 R4_CIN6.2 VR10_CIN6.3
NetC29_CIN6_2: C29_CIN6.2 R6_CIN6.1 VR10_CIN6.1
NetC29_CIN7_1: C29_CIN7.1 R4_CIN7.2 VR10_CIN7.3
NetC29_CIN7_2: C29_CIN7.2 R6_CIN7.1 VR10_CIN7.1
NetC29_CIN8_1: C29_CIN8.1 R4_CIN8.2 VR10_CIN8.3
NetC29_CIN8_2: C29_CIN8.2 R6_CIN8.1 VR10_CIN8.1
NetC30_CIN1_1: C30_CIN1.1 U6_CIN1.6
NetC30_CIN1_2: C30_CIN1.2 VR2_CIN1.1 VR3_CIN1.1
NetC30_CIN2_1: C30_CIN2.1 U6_CIN2.6
NetC30_CIN2_2: C30_CIN2.2 VR2_CIN2.1 VR3_CIN2.1
NetC30_CIN3_1: C30_CIN3.1 U6_CIN3.6
NetC30_CIN3_2: C30_CIN3.2 VR2_CIN3.1 VR3_CIN3.1
NetC30_CIN4_1: C30_CIN4.1 U6_CIN4.6
NetC30_CIN4_2: C30_CIN4.2 VR2_CIN4.1 VR3_CIN4.1
NetC30_CIN5_1: C30_CIN5.1 U6_CIN5.6
NetC30_CIN5_2: C30_CIN5.2 VR2_CIN5.1 VR3_CIN5.1
NetC30_CIN6_1: C30_CIN6.1 U6_CIN6.6
NetC30_CIN6_2: C30_CIN6.2 VR2_CIN6.1 VR3_CIN6.1
NetC30_CIN7_1: C30_CIN7.1 U6_CIN7.6
NetC30_CIN7_2: C30_CIN7.2 VR2_CIN7.1 VR3_CIN7.1
NetC30_CIN8_1: C30_CIN8.1 U6_CIN8.6
NetC30_CIN8_2: C30_CIN8.2 VR2_CIN8.1 VR3_CIN8.1
NetC31_CIN1_1: C31_CIN1.1 R46_CIN1.1
NetC31_CIN1_2: C31_CIN1.2 VR11_CIN1.1
NetC31_CIN2_1: C31_CIN2.1 R46_CIN2.1
NetC31_CIN2_2: C31_CIN2.2 VR11_CIN2.1
NetC31_CIN3_1: C31_CIN3.1 R46_CIN3.1
NetC31_CIN3_2: C31_CIN3.2 VR11_CIN3.1
NetC31_CIN4_1: C31_CIN4.1 R46_CIN4.1
NetC31_CIN4_2: C31_CIN4.2 VR11_CIN4.1
NetC31_CIN5_1: C31_CIN5.1 R46_CIN5.1
NetC31_CIN5_2: C31_CIN5.2 VR11_CIN5.1
NetC31_CIN6_1: C31_CIN6.1 R46_CIN6.1
NetC31_CIN6_2: C31_CIN6.2 VR11_CIN6.1
NetC31_CIN7_1: C31_CIN7.1 R46_CIN7.1
NetC31_CIN7_2: C31_CIN7.2 VR11_CIN7.1
NetC31_CIN8_1: C31_CIN8.1 R46_CIN8.1
NetC31_CIN8_2: C31_CIN8.2 VR11_CIN8.1
NetC32_CIN1_1: C32_CIN1.1 VR11_CIN1.3
NetC32_CIN1_2: C32_CIN1.2 R47_CIN1.1
NetC32_CIN2_1: C32_CIN2.1 VR11_CIN2.3
NetC32_CIN2_2: C32_CIN2.2 R47_CIN2.1
NetC32_CIN3_1: C32_CIN3.1 VR11_CIN3.3
NetC32_CIN3_2: C32_CIN3.2 R47_CIN3.1
NetC32_CIN4_1: C32_CIN4.1 VR11_CIN4.3
NetC32_CIN4_2: C32_CIN4.2 R47_CIN4.1
NetC32_CIN5_1: C32_CIN5.1 VR11_CIN5.3
NetC32_CIN5_2: C32_CIN5.2 R47_CIN5.1
NetC32_CIN6_1: C32_CIN6.1 VR11_CIN6.3
NetC32_CIN6_2: C32_CIN6.2 R47_CIN6.1
NetC32_CIN7_1: C32_CIN7.1 VR11_CIN7.3
NetC32_CIN7_2: C32_CIN7.2 R47_CIN7.1
NetC32_CIN8_1: C32_CIN8.1 VR11_CIN8.3
NetC32_CIN8_2: C32_CIN8.2 R47_CIN8.1
NetC33_CIN1_1: C33_CIN1.1 R5_CIN1.1 U7_CIN1.2 VR11_CIN1.2
NetC33_CIN2_1: C33_CIN2.1 R5_CIN2.1 U7_CIN2.2 VR11_CIN2.2
NetC33_CIN3_1: C33_CIN3.1 R5_CIN3.1 U7_CIN3.2 VR11_CIN3.2
NetC33_CIN4_1: C33_CIN4.1 R5_CIN4.1 U7_CIN4.2 VR11_CIN4.2
NetC33_CIN5_1: C33_CIN5.1 R5_CIN5.1 U7_CIN5.2 VR11_CIN5.2
NetC33_CIN6_1: C33_CIN6.1 R5_CIN6.1 U7_CIN6.2 VR11_CIN6.2
NetC33_CIN7_1: C33_CIN7.1 R5_CIN7.1 U7_CIN7.2 VR11_CIN7.2
NetC33_CIN8_1: C33_CIN8.1 R5_CIN8.1 U7_CIN8.2 VR11_CIN8.2
NetC34_1: C34.1 R29.2 R57.1 U8.2
NetC35_1: C35.1 R33.2 R58.1 U3.2
NetC36_COUT1_1: C36_COUT1.1 R37_COUT1.2 R60_COUT1.1 U4_COUT1.2
NetC36_COUT2_1: C36_COUT2.1 R37_COUT2.2 R60_COUT2.1 U4_COUT2.2
NetC37_1: C37.1 C41.2 R32.1 R61.2
NetC37_2: C37.2 J5.1
NetC38_1: C38.1 C42.2 R36.1 R62.2
NetC38_2: C38.2 J6.1
NetC39_COUT1_2: C39_COUT1.2 J3_COUT1.2
NetC39_COUT2_2: C39_COUT2.2 J3_COUT2.2
NetC40_COUT1_1: C40_COUT1.1 C51_COUT1.2 R56_COUT1.1 R65_COUT1.2
NetC40_COUT1_2: C40_COUT1.2 J3_COUT1.3
NetC40_COUT2_1: C40_COUT2.1 C51_COUT2.2 R56_COUT2.1 R65_COUT2.2
NetC40_COUT2_2: C40_COUT2.2 J3_COUT2.3
NetC41_1: C41.1 R31.1 R32.2 U8.5
NetC42_1: C42.1 R35.1 R36.2 U3.6
NetC43_1: C43.1 R52.2 R59.1 U9.2
NetC43_2: C43.2 R59.2 R66.1 R67.2 R68.1
NetC45_1: C45.1 D4.2 D6.2 U10.1
NetC46_2: C46.2 D3.1 D5.1 U11.2
NetC50_COUT1_1: C50_COUT1.1 D10_COUT1.2 D10_COUT1.4 D10_COUT1.6 D10_COUT1.8 D10_COUT1.10 D10_COUT1.12 D10_COUT1.14 D10_COUT1.16 D10_COUT1.18 D10_COUT1.20 R69_COUT1.2
NetC50_COUT2_1: C50_COUT2.1 D10_COUT2.2 D10_COUT2.4 D10_COUT2.6 D10_COUT2.8 D10_COUT2.10 D10_COUT2.12 D10_COUT2.14 D10_COUT2.16 D10_COUT2.18 D10_COUT2.20 R69_COUT2.2
NetC51_COUT1_1: C51_COUT1.1 R55_COUT1.1 R56_COUT1.2 U5_COUT1.2
NetC51_COUT2_1: C51_COUT2.1 R55_COUT2.1 R56_COUT2.2 U5_COUT2.2
NetD1_1: D1.1 Q1.2 R53.1
NetD1_2: D1.2 D2.1 U9.6
NetD2_2: D2.2 Q2.2 R54.2
NetD3_2: D3.2 D4.1 T1.3
NetD5_2: D5.2 D6.1 T1.5
NetD10_COUT1_1: D10_COUT1.1 U12_COUT1.1
NetD10_COUT1_3: D10_COUT1.3 U12_COUT1.18
NetD10_COUT1_5: D10_COUT1.5 U12_COUT1.17
NetD10_COUT1_7: D10_COUT1.7 U12_COUT1.16
NetD10_COUT1_9: D10_COUT1.9 U12_COUT1.15
NetD10_COUT1_11: D10_COUT1.11 U12_COUT1.14
NetD10_COUT1_13: D10_COUT1.13 U12_COUT1.13
NetD10_COUT1_15: D10_COUT1.15 U12_COUT1.12
NetD10_COUT1_17: D10_COUT1.17 U12_COUT1.11
NetD10_COUT1_19: D10_COUT1.19 U12_COUT1.10
NetD10_COUT2_1: D10_COUT2.1 U12_COUT2.1
NetD10_COUT2_3: D10_COUT2.3 U12_COUT2.18
NetD10_COUT2_5: D10_COUT2.5 U12_COUT2.17
NetD10_COUT2_7: D10_COUT2.7 U12_COUT2.16
NetD10_COUT2_9: D10_COUT2.9 U12_COUT2.15
NetD10_COUT2_11: D10_COUT2.11 U12_COUT2.14
NetD10_COUT2_13: D10_COUT2.13 U12_COUT2.13
NetD10_COUT2_15: D10_COUT2.15 U12_COUT2.12
NetD10_COUT2_17: D10_COUT2.17 U12_COUT2.11
NetD10_COUT2_19: D10_COUT2.19 U12_COUT2.10
NetJ4_CIN1_1: J4_CIN1.1 R25_CIN1.1
NetJ4_CIN1_2: J4_CIN1.2 R26_CIN1.1
NetJ4_CIN2_1: J4_CIN2.1 R25_CIN2.1
NetJ4_CIN2_2: J4_CIN2.2 R26_CIN2.1
NetJ4_CIN3_1: J4_CIN3.1 R25_CIN3.1
NetJ4_CIN3_2: J4_CIN3.2 R26_CIN3.1
NetJ4_CIN4_1: J4_CIN4.1 R25_CIN4.1
NetJ4_CIN4_2: J4_CIN4.2 R26_CIN4.1
NetJ4_CIN5_1: J4_CIN5.1 R25_CIN5.1
NetJ4_CIN5_2: J4_CIN5.2 R26_CIN5.1
NetJ4_CIN6_1: J4_CIN6.1 R25_CIN6.1
NetJ4_CIN6_2: J4_CIN6.2 R26_CIN6.1
NetJ4_CIN7_1: J4_CIN7.1 R25_CIN7.1
NetJ4_CIN7_2: J4_CIN7.2 R26_CIN7.1
NetJ4_CIN8_1: J4_CIN8.1 R25_CIN8.1
NetJ4_CIN8_2: J4_CIN8.2 R26_CIN8.1
NetJ7_1: J7.1 R68.2
NetQ1_3: Q1.3 R66.2
NetQ2_3: Q2.3 R67.1
NetR5_CIN1_2: R5_CIN1.2 VR10_CIN1.2
NetR5_CIN2_2: R5_CIN2.2 VR10_CIN2.2
NetR5_CIN3_2: R5_CIN3.2 VR10_CIN3.2
NetR5_CIN4_2: R5_CIN4.2 VR10_CIN4.2
NetR5_CIN5_2: R5_CIN5.2 VR10_CIN5.2
NetR5_CIN6_2: R5_CIN6.2 VR10_CIN6.2
NetR5_CIN7_2: R5_CIN7.2 VR10_CIN7.2
NetR5_CIN8_2: R5_CIN8.2 VR10_CIN8.2
NetR7_2: R7.2 U9.3
NetR8_COUT1_2: R8_COUT1.2 R15_COUT1.2 U5_COUT1.5
NetR8_COUT2_2: R8_COUT2.2 R15_COUT2.2 U5_COUT2.5
NetR9_2: R9.2 U1.3
NetR10_2: R10.2 U1.5
NetR11_CIN1_2: R11_CIN1.2 U2_CIN1.3
NetR11_CIN2_2: R11_CIN2.2 U2_CIN2.3
NetR11_CIN3_2: R11_CIN3.2 U2_CIN3.3
NetR11_CIN4_2: R11_CIN4.2 U2_CIN4.3
NetR11_CIN5_2: R11_CIN5.2 U2_CIN5.3
NetR11_CIN6_2: R11_CIN6.2 U2_CIN6.3
NetR11_CIN7_2: R11_CIN7.2 U2_CIN7.3
NetR11_CIN8_2: R11_CIN8.2 U2_CIN8.3
NetR12_CIN1_2: R12_CIN1.2 U2_CIN1.5
NetR12_CIN2_2: R12_CIN2.2 U2_CIN2.5
NetR12_CIN3_2: R12_CIN3.2 U2_CIN3.5
NetR12_CIN4_2: R12_CIN4.2 U2_CIN4.5
NetR12_CIN5_2: R12_CIN5.2 U2_CIN5.5
NetR12_CIN6_2: R12_CIN6.2 U2_CIN6.5
NetR12_CIN7_2: R12_CIN7.2 U2_CIN7.5
NetR12_CIN8_2: R12_CIN8.2 U2_CIN8.5
NetR13_2: R13.2 R30.2 U8.6
NetR14_2: R14.2 R34.2 U3.5
NetR16_2: R16.2 R17.1 VR8.1
NetR18_2: R18.2 R19.1 VR8.3
NetR20_CIN1_2: R20_CIN1.2 R22_CIN1.1 VR9_CIN1.1
NetR20_CIN2_2: R20_CIN2.2 R22_CIN2.1 VR9_CIN2.1
NetR20_CIN3_2: R20_CIN3.2 R22_CIN3.1 VR9_CIN3.1
NetR20_CIN4_2: R20_CIN4.2 R22_CIN4.1 VR9_CIN4.1
NetR20_CIN5_2: R20_CIN5.2 R22_CIN5.1 VR9_CIN5.1
NetR20_CIN6_2: R20_CIN6.2 R22_CIN6.1 VR9_CIN6.1
NetR20_CIN7_2: R20_CIN7.2 R22_CIN7.1 VR9_CIN7.1
NetR20_CIN8_2: R20_CIN8.2 R22_CIN8.1 VR9_CIN8.1
NetR21_CIN1_2: R21_CIN1.2 R23_CIN1.1 VR9_CIN1.3
NetR21_CIN2_2: R21_CIN2.2 R23_CIN2.1 VR9_CIN2.3
NetR21_CIN3_2: R21_CIN3.2 R23_CIN3.1 VR9_CIN3.3
NetR21_CIN4_2: R21_CIN4.2 R23_CIN4.1 VR9_CIN4.3
NetR21_CIN5_2: R21_CIN5.2 R23_CIN5.1 VR9_CIN5.3
NetR21_CIN6_2: R21_CIN6.2 R23_CIN6.1 VR9_CIN6.3
NetR21_CIN7_2: R21_CIN7.2 R23_CIN7.1 VR9_CIN7.3
NetR21_CIN8_2: R21_CIN8.2 R23_CIN8.1 VR9_CIN8.3
NetR29_1: R29.1 R50_CIN1.2 R50_CIN2.2 R50_CIN3.2 R50_CIN4.2 R50_CIN5.2 R50_CIN6.2 R50_CIN7.2 R50_CIN8.2 S2.9
NetR33_1: R33.1 S2.10 VR4_CIN1.2 VR4_CIN2.2 VR4_CIN3.2 VR4_CIN4.2 VR4_CIN5.2 VR4_CIN6.2 VR4_CIN7.2 VR4_CIN8.2
NetR43_CIN1_1: R43_CIN1.1 R45_CIN1.1 U6_CIN1.8
NetR43_CIN1_2: R43_CIN1.2 S1_CIN1.2
NetR43_CIN2_1: R43_CIN2.1 R45_CIN2.1 U6_CIN2.8
NetR43_CIN2_2: R43_CIN2.2 S1_CIN2.2
NetR43_CIN3_1: R43_CIN3.1 R45_CIN3.1 U6_CIN3.8
NetR43_CIN3_2: R43_CIN3.2 S1_CIN3.2
NetR43_CIN4_1: R43_CIN4.1 R45_CIN4.1 U6_CIN4.8
NetR43_CIN4_2: R43_CIN4.2 S1_CIN4.2
NetR43_CIN5_1: R43_CIN5.1 R45_CIN5.1 U6_CIN5.8
NetR43_CIN5_2: R43_CIN5.2 S1_CIN5.2
NetR43_CIN6_1: R43_CIN6.1 R45_CIN6.1 U6_CIN6.8
NetR43_CIN6_2: R43_CIN6.2 S1_CIN6.2
NetR43_CIN7_1: R43_CIN7.1 R45_CIN7.1 U6_CIN7.8
NetR43_CIN7_2: R43_CIN7.2 S1_CIN7.2
NetR43_CIN8_1: R43_CIN8.1 R45_CIN8.1 U6_CIN8.8
NetR43_CIN8_2: R43_CIN8.2 S1_CIN8.2
NetR44_COUT1_1: R44_COUT1.1 R70_COUT1.2 U12_COUT1.8
NetR44_COUT1_2: R44_COUT1.2 U12_COUT1.6 U12_COUT1.7
NetR44_COUT2_1: R44_COUT2.1 R70_COUT2.2 U12_COUT2.8
NetR44_COUT2_2: R44_COUT2.2 U12_COUT2.6 U12_COUT2.7
NetR45_CIN1_2: R45_CIN1.2 S1_CIN1.3
NetR45_CIN2_2: R45_CIN2.2 S1_CIN2.3
NetR45_CIN3_2: R45_CIN3.2 S1_CIN3.3
NetR45_CIN4_2: R45_CIN4.2 S1_CIN4.3
NetR45_CIN5_2: R45_CIN5.2 S1_CIN5.3
NetR45_CIN6_2: R45_CIN6.2 S1_CIN6.3
NetR45_CIN7_2: R45_CIN7.2 S1_CIN7.3
NetR45_CIN8_2: R45_CIN8.2 S1_CIN8.3
NetR52_1: R52.1 S2.13
NetR61_1: R61.1 U8.7
NetR62_1: R62.1 U3.7
NetR63_COUT1_1: R63_COUT1.1 U5_COUT1.7
NetR63_COUT2_1: R63_COUT2.1 U5_COUT2.7
NetR64_COUT1_2: R64_COUT1.2 U12_COUT1.5
NetR64_COUT2_2: R64_COUT2.2 U12_COUT2.5
NetR65_COUT1_1: R65_COUT1.1 U5_COUT1.1
NetR65_COUT2_1: R65_COUT2.1 U5_COUT2.1
NetS1_CIN1_1: S1_CIN1.1 U6_CIN1.1
NetS1_CIN2_1: S1_CIN2.1 U6_CIN2.1
NetS1_CIN3_1: S1_CIN3.1 U6_CIN3.1
NetS1_CIN4_1: S1_CIN4.1 U6_CIN4.1
NetS1_CIN5_1: S1_CIN5.1 U6_CIN5.1
NetS1_CIN6_1: S1_CIN6.1 U6_CIN6.1
NetS1_CIN7_1: S1_CIN7.1 U6_CIN7.1
NetS1_CIN8_1: S1_CIN8.1 U6_CIN8.1
NEUTRAL: J8.3 T1.2
pads on no net: F1.1@20087,20953 F1.2@20087,21953 J1.0 J1.2 J4_CIN1.0 J4_CIN2.0 J4_CIN3.0 J4_CIN4.0 J4_CIN5.0 J4_CIN6.0 J4_CIN7.0 J4_CIN8.0 J5.0 J5.2 J6.0 J6.2 J7.0 J7.2 J8.2 U4_COUT1.5 U4_COUT1.6 U4_COUT1.7 U4_COUT2.5 U4_COUT2.6 U4_COUT2.7 U7_CIN1.1 U7_CIN1.5 U7_CIN1.8 U7_CIN2.1 U7_CIN2.5 U7_CIN2.8 U7_CIN3.1 U7_CIN3.5 U7_CIN3.8 U7_CIN4.1 U7_CIN4.5 U7_CIN4.8 U7_CIN5.1 U7_CIN5.5 U7_CIN5.8 U7_CIN6.1 U7_CIN6.5 U7_CIN6.8 U7_CIN7.1 U7_CIN7.5 U7_CIN7.8 U7_CIN8.1 U7_CIN8.5 U7_CIN8.8 U9.1 U9.5 U9.8 VR1.MNT VR2_CIN1.MNT VR2_CIN2.MNT VR2_CIN3.MNT VR2_CIN4.MNT VR2_CIN5.MNT VR2_CIN6.MNT VR2_CIN7.MNT VR2_CIN8.MNT VR3_CIN1.MNT VR3_CIN2.MNT VR3_CIN3.MNT VR3_CIN4.MNT VR3_CIN5.MNT VR3_CIN6.MNT VR3_CIN7.MNT VR3_CIN8.MNT VR4_CIN1.MNT VR4_CIN2.MNT VR4_CIN3.MNT VR4_CIN4.MNT VR4_CIN5.MNT VR4_CIN6.MNT VR4_CIN7.MNT VR4_CIN8.MNT VR5.MNT VR6.MNT VR7_COUT1.MNT VR7_COUT2.MNT VR8.MNT VR9_CIN1.MNT VR9_CIN2.MNT VR9_CIN3.MNT VR9_CIN4.MNT VR9_CIN5.MNT VR9_CIN6.MNT VR9_CIN7.MNT VR9_CIN8.MNT VR10_CIN1.MNT VR10_CIN2.MNT VR10_CIN3.MNT VR10_CIN4.MNT VR10_CIN5.MNT VR10_CIN6.MNT VR10_CIN7.MNT VR10_CIN8.MNT VR11_CIN1.MNT VR11_CIN2.MNT VR11_CIN3.MNT VR11_CIN4.MNT VR11_CIN5.MNT VR11_CIN6.MNT VR11_CIN7.MNT VR11_CIN8.MNT

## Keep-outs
Keep-Out Layer:
  the board outline again, w50

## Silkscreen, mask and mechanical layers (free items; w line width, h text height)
Mechanical 16:
  drawing of 1698 lines, arcs and shapes, not listed
  text "1" at 1576.34,15715 h70
  text "2" at 4357,15715 h70
  text "3" at 7136.34,15715 h70
  text "4" at 9933.01,15715 h70
  text "5" at 12716.35,15715 h70
  text "6" at 15507,15715 h70
  text "7" at 18307,15715 h70
  text "8" at 21087,15715 h70
  text "A" at 325,13857 h70
  text "A" at 22325,13857 h70
  text "B" at 325,9927 h70
  text "B" at 22325,9927 h70
  text "C" at 325,6007 h70
  text "C" at 22325,6007 h70
  text "D" at 325,2077 h70
  text "D" at 22325,2077 h70
  text "ENGINEER:" at 17750,1600 h45
  text "TITLE:" at 19250,1600 h45
  text "PCB DESIGNER:" at 17750,1305 h45
  text "n" at 16976,1228 h35
  text "n" at 16976,1228 h35
  text "T" at 16450,1227 h35
  text "T" at 16450,1227 h35
  text "h" at 16495,1227 h35
  text "h" at 16495,1227 h35
  text "i" at 16535.33,1227 h35
  text "i" at 16535.33,1227 h35
  text "n" at 16564,1227 h35
  text "n" at 16564,1227 h35
  text "k" at 16610,1227 h35
  text "k" at 16610,1227 h35
  text "i" at 16670.67,1227 h35
  text "i" at 16670.67,1227 h35
  text "t" at 16696.67,1227 h35
  text "t" at 16696.67,1227 h35
  text "," at 16727.67,1226.67 h35
  text "," at 16727.67,1226.67 h35
  text "D" at 16780,1227 h35
  text "D" at 16780,1227 h35
  text "e" at 16827,1227 h35
  text "e" at 16827,1227 h35
  text "s" at 16868,1227 h35
  text "s" at 16868,1227 h35
  text "i" at 16900.33,1227 h35
  text "i" at 16900.33,1227 h35
  text "g" at 16929,1226.66 h35
  text "g" at 16929,1226.66 h35
  text "i" at 17040.33,1227 h35
  text "i" at 17040.33,1227 h35
  text "t" at 17064.67,1227 h35
  text "t" at 17064.67,1227 h35
  text "," at 17095.67,1226.67 h35
  text "," at 17095.67,1226.67 h35
  text "B" at 17146,1227 h35
  text "B" at 17146,1227 h35
  text "u" at 17194,1227 h35
  text "u" at 17194,1227 h35
  text "i" at 17231.33,1227 h35
  text "i" at 17231.33,1227 h35
  text "l" at 17261,1227 h35
  text "l" at 17261,1227 h35
  text "d" at 17283,1227 h35
  text "d" at 17283,1227 h35
  text "i" at 17347.67,1227 h35
  text "i" at 17347.67,1227 h35
  text "t" at 17373.67,1227 h35
  text "t" at 17373.67,1227 h35
  text "DATE:" at 17750,1000 h45
  text "PART NO.:" at 19250,1000 h45
  text "REV:" at 21350,1000 h45
  text "Altium Limited" at 16450,900 h70
  text ".PRINT_DATE" at 17800,880 h70
  text "12a Rodborough Rd" at 16450,800 h70
  text "Frenchs Forest" at 16450,700 h70
  text "FILE NAME:" at 17750,700 h45
  text "DWG NO:" at 19250,700 h45
  text "SCALE:" at 21350,700 h45
  text "NSW 2086" at 16450,600 h70
  text ".PCB_FILE_NAME_NO_PATH" at 17800,580 h70
  text "1" at 1576.34,325 h70
  text "2" at 4357,325 h70
  text "3" at 7136.34,325 h70
  text "4" at 9933.01,325 h70
  text "5" at 12716.35,325 h70
  text "6" at 15507,325 h70
  text "7" at 18307,325 h70
  text "8" at 21087,325 h70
